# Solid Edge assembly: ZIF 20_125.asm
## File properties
Title: Zylinder
Author: bmolnar
Template: iso metric assembly.asm
Last saved by: bmolnar
Revision: 25
Application: Solid Edge
Username: bmolnar
Dokumentum tartalom típus: 1
Document Number: ZIF 20/125
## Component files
Mutter.par
Profilrohr.par
Kolbenstange.par
Kit_2.par
Kit_1.par
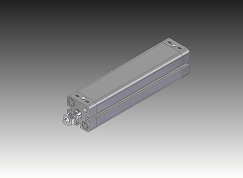
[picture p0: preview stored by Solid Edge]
